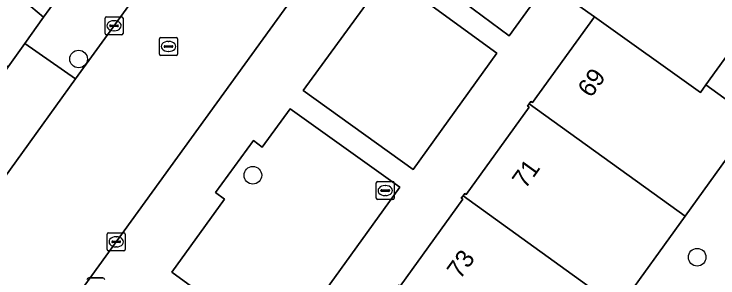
# Model space of a CAD drawing. Extents: x 159674 to 160531, y 382172 to 382904.
# Drawn here: x 160023.5 to 160062.61, y 382484.03 to 382498.68 of the extents above; entities that cross this region are included whole.
import ezdxf

# ---------------------------------------------------------------- set-up
doc = ezdxf.new("R2010")
doc.units = 0
for name, color, linetype in [('IMGEO_Boom', 7, 'Continuous'), ('IMGEO_Erf', 7, 'Continuous'), ('IMGEO_Groenvoorziening', 7, 'Continuous'), ('IMGEO_Kolk', 7, 'Continuous'), ('IMGEO_Lichtmast', 7, 'Continuous'), ('IMGEO_Pand', 7, 'Continuous'), ('IMGEO_Pand_nummerreeks', 7, 'Continuous'), ('IMGEO_Rijbaan_lokaal_open', 7, 'Continuous'), ('IMGEO_Rioolput', 7, 'Continuous'), ('IMGEO_Voetpad_open', 7, 'Continuous')]:
    doc.layers.add(name, color=color, linetype=linetype)

msp = doc.modelspace()

# ---------------------------------------------------------------- linework, layer by layer
at = {"layer": 'IMGEO_Boom'}
for centre in [(160027.084, 382496.189), (160036.769, 382489.734), (160061.457, 382485.183)]:
    msp.add_circle(centre, 0.489, dxfattribs=at)
at = {"layer": 'IMGEO_Erf'}
msp.add_lwpolyline([(160076.424, 382483.871), (160071.352, 382487.534), (160071.288, 382487.445), (160071.027, 382487.633), (160077.341, 382496.414), (160075.053, 382498.052), (160074.062, 382498.749), (160074.3, 382499.148), (160068.355, 382503.451), (160068.166, 382503.189), (160068.076, 382503.253), (160065.037, 382499.042), (160065.126, 382498.977), (160065.02, 382498.831), (160064.936, 382498.714), (160064.847, 382498.778), (160061.947, 382494.76), (160064.742, 382492.743), (160064.554, 382492.484), (160064.464, 382492.549), (160060.795, 382487.463), (160057.11, 382482.355)], dxfattribs=at)
at = {"layer": 'IMGEO_Groenvoorziening'}
msp.add_lwpolyline([(160000.39, 382510.343), (160016.108, 382498.067), (160019.147, 382498.852), (160023.178, 382495.76), (160024.091, 382497.056), (160025.139, 382498.506), (160018.782, 382503.868), (160016.198, 382501.889), (160014.065, 382502.61), (160011.22, 382506.317), (160012.588, 382507.249), (160012.341, 382507.62), (160010.346, 382510.606), (160005.961, 382517.17), (160000.813, 382513.681), (159999.314, 382511.482), (159997.867, 382511.987), (159999.736, 382514.682), (160005.174, 382518.349), (159999.274, 382527.182)], dxfattribs=at)
for points in [[(160064.007, 382515.422), (160059.119, 382518.953), (160056.953, 382518.389), (160056.45, 382517.716), (160054.947, 382515.702), (160054.359, 382516.125), (160052.266, 382513.231), (160052.857, 382512.796), (160047.971, 382506.042), (160047.498, 382506.461), (160046.092, 382504.454), (160046.544, 382504.014), (160045.003, 382501.928), (160051.006, 382497.467), (160061.941, 382512.569)], [(160050.322, 382496.516), (160044.283, 382500.917), (160039.565, 382494.435), (160045.675, 382490.06)], [(160044.933, 382489.07), (160038.837, 382493.417), (160037.289, 382491.287), (160036.806, 382491.669), (160034.701, 382488.784), (160035.196, 382488.416), (160032.259, 382484.362), (160038.348, 382479.927)]]:
    msp.add_lwpolyline(points, close=True, dxfattribs=at)
at = {"layer": 'IMGEO_Kolk'}
for p, q in [((160028.627, 382498.534), (160029.479, 382498.534)), ((160028.552, 382497.608), (160028.552, 382498.46)), ((160029.04, 382498.314), (160029.065, 382498.314)), ((160029.553, 382498.46), (160029.553, 382497.608)), ((160028.811, 382498.028), (160028.811, 382498.04)), ((160029.249, 382497.991), (160028.851, 382497.991)), ((160028.854, 382498.077), (160029.252, 382498.077)), ((160029.063, 382497.754), (160029.038, 382497.754)), ((160029.295, 382498.04), (160029.295, 382498.028)), ((160029.479, 382497.534), (160028.627, 382497.534)), ((160028.677, 382485.612), (160028.677, 382486.464)), ((160028.752, 382486.538), (160029.604, 382486.538)), ((160029.678, 382486.464), (160029.678, 382485.612)), ((160028.936, 382486.032), (160028.936, 382486.044)), ((160029.374, 382485.995), (160028.976, 382485.995)), ((160028.979, 382486.081), (160029.377, 382486.081)), ((160029.165, 382486.318), (160029.19, 382486.318)), ((160029.42, 382486.044), (160029.42, 382486.032)), ((160029.188, 382485.758), (160029.163, 382485.758)), ((160029.604, 382485.538), (160028.752, 382485.538))]:
    msp.add_line(p, q, dxfattribs=at)
for points in [[(160028.627, 382498.534), (160029.479, 382498.534)], [(160028.552, 382497.608), (160028.552, 382498.46)], [(160029.553, 382498.46), (160029.553, 382497.608)], [(160029.479, 382497.534), (160028.627, 382497.534)], [(160028.677, 382485.612), (160028.677, 382486.464)], [(160028.752, 382486.538), (160029.604, 382486.538)], [(160029.678, 382486.464), (160029.678, 382485.612)], [(160029.604, 382485.538), (160028.752, 382485.538)]]:
    msp.add_lwpolyline(points, dxfattribs=at)
for centre, radius, start, end in [((160028.629, 382498.458), 0.0765, 91.552, 178.448), ((160028.629, 382498.458), 0.0765, 91.552, 178.448), ((160029.477, 382498.458), 0.0765, 1.552, 88.448), ((160029.477, 382498.458), 0.0765, 1.552, 88.448), ((160028.851, 382498.037), 0.0403, 85.8775, 175.7526), ((160028.848, 382498.027), 0.0366, 178.938, 274.7102), ((160029.252, 382498.034), 0.043, 264.8664, 352.4533), ((160029.256, 382498.039), 0.0386, 1.7309, 96.639), ((160028.629, 382497.61), 0.0765, 181.552, 268.448), ((160028.629, 382497.61), 0.0765, 181.552, 268.448), ((160029.477, 382497.61), 0.0765, 271.552, 358.448), ((160029.477, 382497.61), 0.0765, 271.552, 358.448), ((160028.754, 382486.462), 0.0765, 91.552, 178.448), ((160028.754, 382486.462), 0.0765, 91.552, 178.448), ((160029.602, 382486.462), 0.0765, 1.552, 88.448), ((160029.602, 382486.462), 0.0765, 1.552, 88.448), ((160028.976, 382486.041), 0.0403, 85.8775, 175.7526), ((160028.973, 382486.031), 0.0366, 178.938, 274.7102), ((160029.377, 382486.038), 0.043, 264.8664, 352.4533), ((160029.381, 382486.043), 0.0386, 1.7309, 96.639), ((160028.754, 382485.614), 0.0765, 181.552, 268.448), ((160028.754, 382485.614), 0.0765, 181.552, 268.448), ((160029.602, 382485.614), 0.0765, 271.552, 358.448), ((160029.602, 382485.614), 0.0765, 271.552, 358.448)]:
    msp.add_arc(centre, radius, start, end, dxfattribs=at)
for centre, major_axis, ratio, start_param, end_param in [((160029.039, 382498.034), (-0.387, 0.002), 0.722429, 4.712389, 7.853982), ((160029.064, 382498.034), (-0.39, 0.002), 0.717154, 1.570796, 4.712389), ((160029.164, 382486.038), (-0.387, 0.002), 0.722429, 4.712389, 7.853982), ((160029.189, 382486.038), (-0.39, 0.002), 0.717154, 1.570796, 4.712389)]:
    msp.add_ellipse(centre, major_axis=major_axis, ratio=ratio, start_param=start_param, end_param=end_param, dxfattribs=at)
at = {"layer": 'IMGEO_Lichtmast'}
for p, q in [((160027.649, 382484.035), (160028.439, 382484.035)), ((160028.439, 382484.035), (160027.649, 382484.035))]:
    msp.add_line(p, q, dxfattribs=at)
for centre, start, end in [((160027.649, 382483.935), 90, 180), ((160027.649, 382483.935), 90, 180), ((160028.439, 382483.935), 0, 90), ((160028.439, 382483.935), 360, 90)]:
    msp.add_arc(centre, 0.1, start, end, dxfattribs=at)
at = {"layer": 'IMGEO_Pand'}
for points in [[(160057.344, 382504.374), (160057.25, 382504.244), (160057.339, 382504.179), (160054.295, 382499.968), (160054.205, 382500.032), (160054.018, 382499.77), (160055.749, 382498.535), (160061.639, 382494.333), (160061.947, 382494.76), (160064.847, 382498.778), (160064.936, 382498.714), (160065.02, 382498.831)], [(160061.947, 382494.76), (160061.639, 382494.333), (160055.749, 382498.535), (160052.313, 382493.771), (160052.223, 382493.836), (160052.129, 382493.706), (160060.795, 382487.463), (160064.464, 382492.549), (160064.554, 382492.484), (160064.742, 382492.743)], [(160052.129, 382493.706), (160052.035, 382493.575), (160052.125, 382493.51), (160048.628, 382488.663), (160048.539, 382488.727), (160048.445, 382488.597), (160057.11, 382482.355), (160060.795, 382487.463)], [(160048.445, 382488.597), (160048.351, 382488.466), (160048.44, 382488.402), (160044.953, 382483.568), (160044.864, 382483.632), (160044.769, 382483.5), (160053.437, 382477.262), (160057.11, 382482.355)]]:
    msp.add_lwpolyline(points, close=True, dxfattribs=at)
at = {"layer": 'IMGEO_Rijbaan_lokaal_open'}
for points in [[(160051.746, 382520.454), (160047.551, 382523.358), (160046.433, 382521.888), (160040.526, 382513.809), (160030.477, 382500), (160026.917, 382495.079), (160020.333, 382485.978), (160000, 382457.874), (159989.893, 382443.905), (159982.977, 382434.345), (159980.776, 382431.302)], [(160017.12, 382469.419), (160041.091, 382502.494)]]:
    msp.add_lwpolyline(points, dxfattribs=at)
msp.add_lwpolyline([(160026.299, 382507.836), (160028.99, 382503.833), (160030.233, 382505.553), (160028.033, 382508.833), (160025.974, 382511.903), (160023.988, 382514.864), (160020.899, 382512.801), (160013.807, 382508.064), (160018.323, 382504.255), (160018.782, 382503.868), (160025.139, 382498.506), (160026.197, 382499.969), (160020.61, 382504.681), (160019.344, 382505.749), (160019.484, 382507.37), (160024.392, 382510.673)], close=True, dxfattribs=at)
at = {"layer": 'IMGEO_Rioolput'}
for p, q in [((160031.652, 382497.386), (160032.504, 382497.386)), ((160031.577, 382496.46), (160031.577, 382497.312)), ((160031.879, 382496.929), (160032.277, 382496.929)), ((160032.065, 382497.166), (160032.09, 382497.166)), ((160032.578, 382497.312), (160032.578, 382496.46)), ((160031.836, 382496.88), (160031.836, 382496.892)), ((160032.274, 382496.843), (160031.876, 382496.843)), ((160032.088, 382496.606), (160032.063, 382496.606)), ((160032.32, 382496.892), (160032.32, 382496.88)), ((160032.504, 382496.386), (160031.652, 382496.386)), ((160043.625, 382488.458), (160043.625, 382489.31)), ((160043.7, 382489.384), (160044.552, 382489.384)), ((160044.113, 382489.164), (160044.138, 382489.164)), ((160044.626, 382489.31), (160044.626, 382488.458)), ((160043.884, 382488.878), (160043.884, 382488.89)), ((160044.322, 382488.841), (160043.924, 382488.841)), ((160043.927, 382488.927), (160044.325, 382488.927)), ((160044.368, 382488.89), (160044.368, 382488.878)), ((160044.552, 382488.384), (160043.7, 382488.384)), ((160044.136, 382488.604), (160044.111, 382488.604))]:
    msp.add_line(p, q, dxfattribs=at)
for points in [[(160031.652, 382497.386), (160032.504, 382497.386)], [(160031.577, 382496.46), (160031.577, 382497.312)], [(160032.578, 382497.312), (160032.578, 382496.46)], [(160032.504, 382496.386), (160031.652, 382496.386)], [(160043.625, 382488.458), (160043.625, 382489.31)], [(160043.7, 382489.384), (160044.552, 382489.384)], [(160044.626, 382489.31), (160044.626, 382488.458)], [(160044.552, 382488.384), (160043.7, 382488.384)]]:
    msp.add_lwpolyline(points, dxfattribs=at)
for centre, radius, start, end in [((160031.654, 382497.31), 0.0765, 91.552, 178.448), ((160031.654, 382497.31), 0.0765, 91.552, 178.448), ((160032.502, 382497.31), 0.0765, 1.552, 88.448), ((160032.502, 382497.31), 0.0765, 1.552, 88.448), ((160031.876, 382496.889), 0.0403, 85.8775, 175.7526), ((160032.281, 382496.891), 0.0386, 1.7309, 96.639), ((160031.873, 382496.879), 0.0366, 178.938, 274.7102), ((160032.277, 382496.886), 0.043, 264.8664, 352.4533), ((160031.654, 382496.462), 0.0765, 181.552, 268.448), ((160031.654, 382496.462), 0.0765, 181.552, 268.448), ((160032.502, 382496.462), 0.0765, 271.552, 358.448), ((160032.502, 382496.462), 0.0765, 271.552, 358.448), ((160043.702, 382489.308), 0.0765, 91.552, 178.448), ((160043.702, 382489.308), 0.0765, 91.552, 178.448), ((160044.55, 382489.308), 0.0765, 1.552, 88.448), ((160044.55, 382489.308), 0.0765, 1.552, 88.448), ((160043.924, 382488.887), 0.0403, 85.8775, 175.7526), ((160043.921, 382488.877), 0.0366, 178.938, 274.7102), ((160044.325, 382488.884), 0.043, 264.8664, 352.4533), ((160044.329, 382488.889), 0.0386, 1.7309, 96.639), ((160043.702, 382488.46), 0.0765, 181.552, 268.448), ((160043.702, 382488.46), 0.0765, 181.552, 268.448), ((160044.55, 382488.46), 0.0765, 271.552, 358.448), ((160044.55, 382488.46), 0.0765, 271.552, 358.448)]:
    msp.add_arc(centre, radius, start, end, dxfattribs=at)
for centre, major_axis, ratio, start_param, end_param in [((160032.064, 382496.886), (-0.387, 0.002), 0.722429, 4.712389, 7.853982), ((160032.089, 382496.886), (-0.39, 0.002), 0.717154, 1.570796, 4.712389), ((160044.112, 382488.884), (-0.387, 0.002), 0.722429, 4.712389, 7.853982), ((160044.137, 382488.884), (-0.39, 0.002), 0.717154, 1.570796, 4.712389)]:
    msp.add_ellipse(centre, major_axis=major_axis, ratio=ratio, start_param=start_param, end_param=end_param, dxfattribs=at)
at = {"layer": 'IMGEO_Voetpad_open'}
for points in [[(160046.298, 382527.781), (160043.699, 382524.182), (160030.233, 382505.553), (160028.99, 382503.833), (160028.435, 382503.065), (160026.75, 382500.735), (160026.219, 382500), (160026.197, 382499.969), (160025.139, 382498.506), (160024.091, 382497.056), (160026.917, 382495.079), (160030.477, 382500), (160040.526, 382513.809), (160046.433, 382521.888), (160047.551, 382523.358), (160059.002, 382539.131)], [(160051.574, 382516.842), (160051.402, 382516.632), (160041.091, 382502.494), (160017.12, 382469.419)], [(160064.007, 382515.422), (160061.941, 382512.569), (160051.006, 382497.467), (160045.003, 382501.928)], [(160044.953, 382483.568), (160048.44, 382488.402), (160048.351, 382488.466), (160048.445, 382488.597), (160048.539, 382488.727), (160048.628, 382488.663), (160052.125, 382493.51), (160052.035, 382493.575), (160052.129, 382493.706), (160052.223, 382493.836), (160052.313, 382493.771), (160055.749, 382498.535), (160054.018, 382499.77)]]:
    msp.add_lwpolyline(points, dxfattribs=at)
for points in [[(160050.322, 382496.516), (160045.675, 382490.06), (160039.565, 382494.435), (160044.283, 382500.917)], [(160026.917, 382495.079), (160024.091, 382497.056), (160023.178, 382495.76), (160019.623, 382490.895), (160017.498, 382488.062), (160020.333, 382485.978)], [(160044.933, 382489.07), (160038.348, 382479.927), (160032.259, 382484.362), (160035.196, 382488.416), (160034.701, 382488.784), (160036.806, 382491.669), (160037.289, 382491.287), (160038.837, 382493.417)]]:
    msp.add_lwpolyline(points, close=True, dxfattribs=at)

# ---------------------------------------------------------------- texts
at = {"layer": 'IMGEO_Pand_nummerreeks'}
for s, rotation, p in [('69', 54.2018, (160055.552, 382493.989)), ('71', 54.1903, (160051.908, 382488.937)), ('73', 54.1961, (160048.284, 382483.913))]:
    msp.add_text(s, height=1, rotation=rotation, dxfattribs=at).set_placement(p)

doc.saveas('drawing.dxf')
